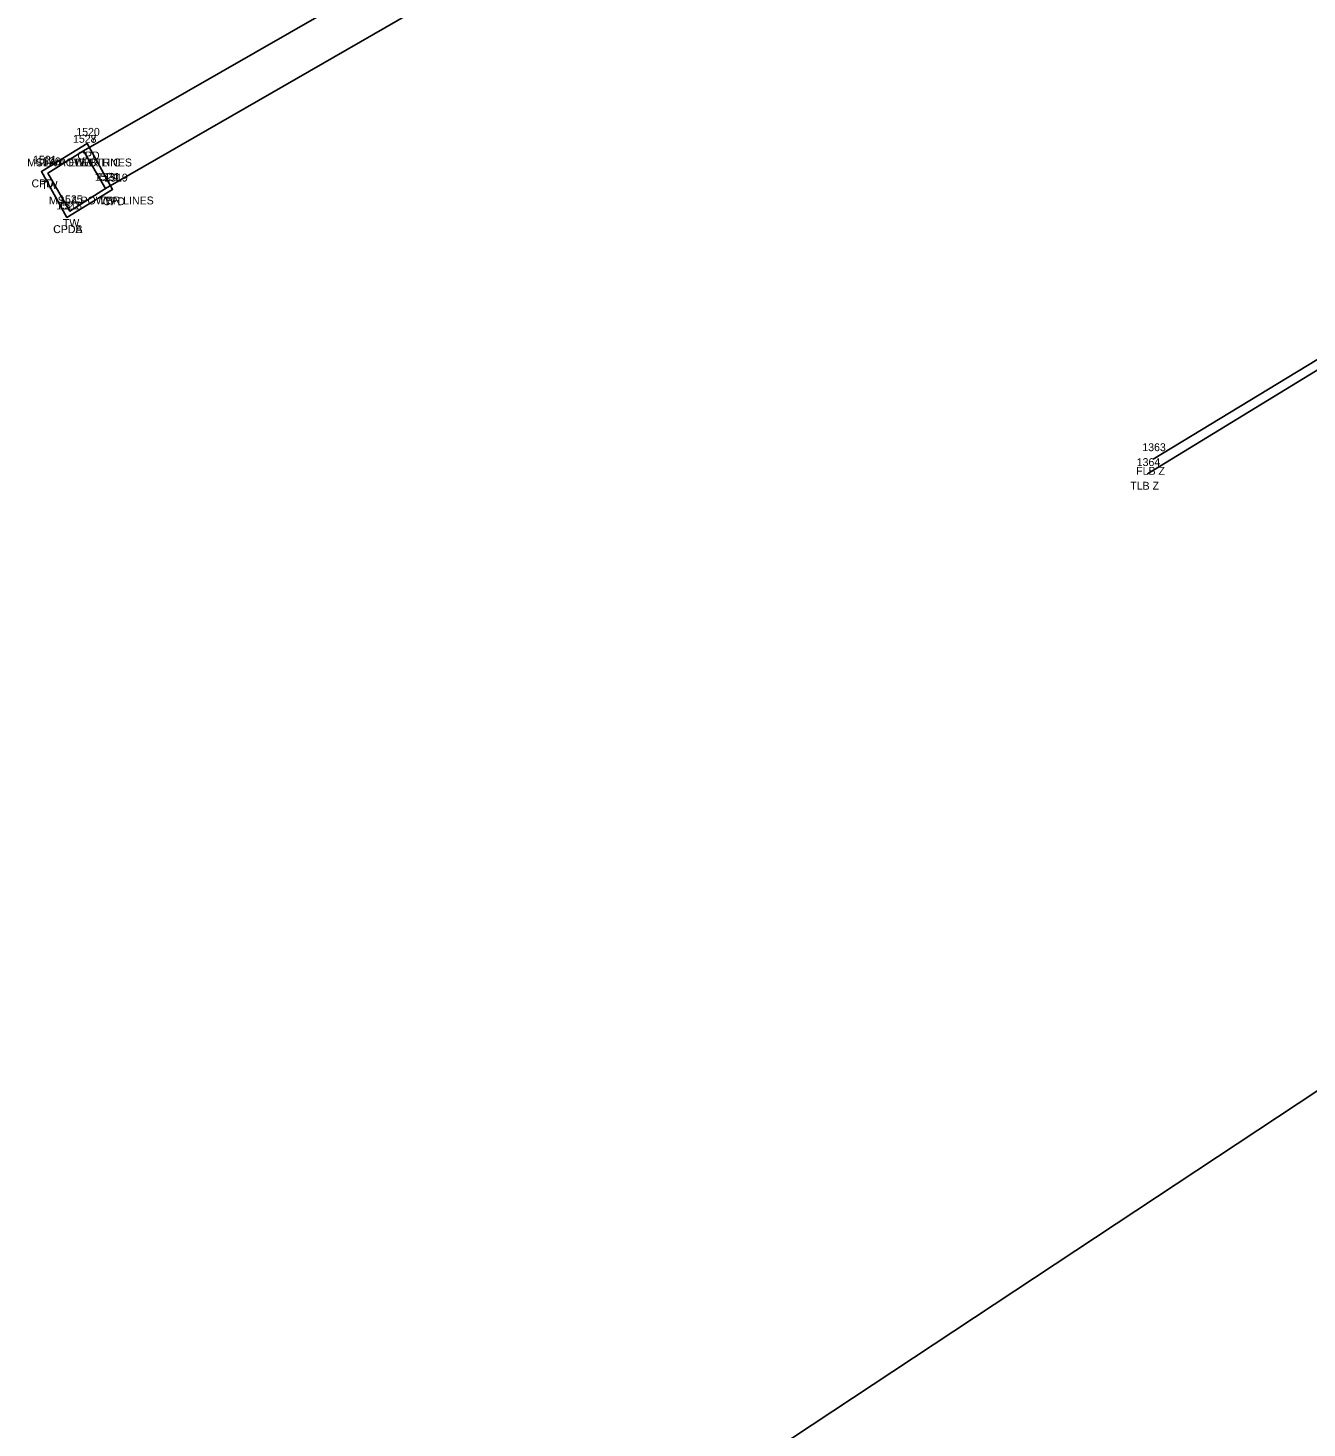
# Model space of a CAD drawing. Extents: x 1812113 to 1819860, y 1177290 to 1181185.
# Drawn here: x 1813398.6 to 1813560.9, y 1178410.7 to 1178588.3 of the extents above; entities that cross this region are included whole.
import ezdxf

# ---------------------------------------------------------------- set-up
doc = ezdxf.new("R2010")
doc.units = 0
for name, color, linetype in [('RD_EX_Conc', 7, 'Continuous'), ('RD_EX_Conc_txCode', 7, 'Continuous'), ('RD_EX_DV_Prop', 7, 'Continuous'), ('RD_EX_Fence_Other', 7, 'Continuous'), ('RD_EX_Fence_Other_txCode', 7, 'Continuous'), ('RD_EX_Misc', 7, 'Continuous'), ('RD_EX_Misc_txCode', 7, 'Continuous'), ('RD_EX_UT', 7, 'Continuous'), ('RD_EX_UT_txCode', 7, 'Continuous'), ('RD_EX_VEG', 7, 'Continuous'), ('RD_EX_VEG_txCode', 7, 'Continuous'), ('RD_PD_PatLn1', 7, 'Continuous'), ('RD_SMD_Locator', 7, 'Continuous')]:
    doc.layers.add(name, color=color, linetype=linetype)

msp = doc.modelspace()

# ---------------------------------------------------------------- linework, layer by layer
at = {"layer": 'RD_EX_Conc'}
msp.add_lwpolyline([(1813403.58, 1178564.28), (1813409.39, 1178567.82), (1813406.16, 1178573.63), (1813400.36, 1178570.09), (1813403.58, 1178564.28)], dxfattribs=at)
at = {"layer": 'RD_EX_DV_Prop'}
msp.add_line((1813493.05, 1178407.69), (1813582.74, 1178466.98), dxfattribs=at)
at = {"layer": 'RD_EX_Fence_Other'}
msp.add_lwpolyline([(1813689.16, 1178653.47), (1813706.15, 1178633.63), (1813541.42, 1178533.61)], dxfattribs=at)
at = {"layer": 'RD_EX_Misc'}
for points in [[(1813405.71, 1178572.74), (1813779.17, 1178786.7), (1813799.35, 1179222.21)], [(1813408.47, 1178567.92), (1813786.33, 1178785.29), (1813804.76, 1179221.83)]]:
    msp.add_lwpolyline(points, dxfattribs=at)
at = {"layer": 'RD_EX_UT'}
msp.add_lwpolyline([(1813405.71, 1178572.74), (1813408.47, 1178567.92), (1813403.94, 1178565.07), (1813401.18, 1178569.89), (1813405.71, 1178572.74)], dxfattribs=at)
at = {"layer": 'RD_EX_VEG'}
msp.add_lwpolyline([(1813569.58, 1178500.76), (1813635.35, 1178535.15), (1813737.8, 1178606.06), (1813775.9, 1178641.25), (1813752.75, 1178672.45), (1813690.46, 1178652.62), (1813708.11, 1178634.09), (1813540.71, 1178531.72)], dxfattribs=at)
at = {"layer": 'RD_PD_PatLn1'}
msp.add_circle((1813408.47, 1178567.92), 0.0417, dxfattribs=at)
msp.add_circle((1813408.47, 1178567.92), 0.0417, dxfattribs=at)
at = {"layer": 'RD_SMD_Locator'}
for centre in [(1813406.16, 1178573.63), (1813405.71, 1178572.74), (1813405.71, 1178572.74), (1813405.71, 1178572.74), (1813400.36, 1178570.09), (1813401.18, 1178569.89), (1813408.47, 1178567.92), (1813408.47, 1178567.92), (1813409.39, 1178567.82), (1813403.94, 1178565.07), (1813403.58, 1178564.28), (1813403.58, 1178564.28), (1813541.42, 1178533.61), (1813540.71, 1178531.72)]:
    msp.add_circle(centre, 0.001, dxfattribs=at)

# ---------------------------------------------------------------- texts
at = {"layer": 'RD_EX_Conc_txCode'}
for s, p in [('1520', (1813404.78, 1178574.63)), ('1521', (1813399.29, 1178571.09)), ('CPD', (1813404.91, 1178571.63)), ('1519', (1813408.33, 1178568.82)), ('CPD', (1813399.1, 1178568.09)), ('1522', (1813402.24, 1178565.28)), ('1518', (1813402.52, 1178565.28)), ('CPD', (1813408.14, 1178565.82)), ('CPDA', (1813401.84, 1178562.28)), ('CPDB', (1813401.86, 1178562.28))]:
    msp.add_text(s, height=1, dxfattribs=at).set_placement(p)
at = {"layer": 'RD_EX_Fence_Other_txCode'}
for s, p in [('1363', (1813540.05, 1178534.61)), ('FLB Z', (1813539.27, 1178531.61))]:
    msp.add_text(s, height=1, dxfattribs=at).set_placement(p)
at = {"layer": 'RD_EX_Misc_txCode'}
for s, p in [('1528', (1813404.36, 1178573.74)), ('MSLA POWER LINES', (1813398.54, 1178570.74)), ('1531', (1813407.4, 1178568.92)), ('MSLA POWER LINES', (1813401.3, 1178565.92))]:
    msp.add_text(s, height=1, dxfattribs=at).set_placement(p)
at = {"layer": 'RD_EX_UT_txCode'}
for s, p in [('1523', (1813404.36, 1178573.74)), ('1527', (1813404.36, 1178573.74)), ('1526', (1813399.81, 1178570.89)), ('TWA ELECTRIC', (1813400.45, 1178570.74)), ('TWB', (1813404.37, 1178570.74)), ('1524', (1813407.12, 1178568.92)), ('TW', (1813400.32, 1178567.89)), ('1525', (1813402.6, 1178566.07)), ('TW', (1813407.61, 1178565.92)), ('TW', (1813403.08, 1178563.07))]:
    msp.add_text(s, height=1, dxfattribs=at).set_placement(p)
at = {"layer": 'RD_EX_VEG_txCode'}
for s, p in [('1364', (1813539.34, 1178532.72)), ('TLB Z', (1813538.52, 1178529.72))]:
    msp.add_text(s, height=1, dxfattribs=at).set_placement(p)

doc.saveas('drawing.dxf')
